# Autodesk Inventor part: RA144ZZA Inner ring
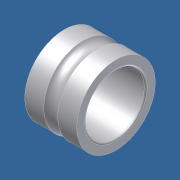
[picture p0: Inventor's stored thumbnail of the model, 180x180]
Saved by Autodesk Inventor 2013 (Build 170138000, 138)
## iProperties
Category: PARTsolutions
Created: 2011-07
Part Number: RA144ZZA Inner ring
Catalog Web Link: www.cadenas.de
Description: Six types ir - Inch system sizes
Document SubType Name: Modeling
Designer: PARTsolutions
Density: 1 g/cm^3
Material: Générique
NB: RA144ZZA Inner ring
NN: Six types ir
NT: Inch system sizes
NBSYN: RA144ZZA Inner ring
LINA: RA144ZZA Inner ring
SD: 3.175
D: 6.350
B: 2.380
B1: 2.779
D1: 7.52
D2: 7.52
C1: 0.58
C2: 0.79
R: 0.08
ORDER: RA144ZZA
CR: 284
COR: 96
CRF: 29
CORF: 10
LSG: 59000
LSO: 70000
MASS: 0.27
ORDER1: R144
WSS: RA144ZA
WDS: RA144ZZA
UTWF: FLR144
FORSS: FLRA144ZA
FORDS: FLRA144ZZA
DA1: 3.9
DA2: 4
DA: 5.5
RAS: 0.08
MASS1: 0.33
VERS: 3
X: 1.587
N: 9
O: 14.954
RB: 0.470
KT: DUMMY
SUPPLIER: NTN
ARTICLENO: RA144ZZA Inner ring
BOMINFO: RA144ZZA Inner ring
CREATOR: CADENAS GmbH
PSOL_IDENT_0: {\\10.0.0.251\ps_data\23d-libs\ntn\ball_roller_bearings\miniature_extra_small_bb\inch_system_sizes\i
PSOL_IDENT_1: ss_ir.prj},189 {VTYP=3D},{NB=RA144ZZA Inner ring},{LINA=RA144ZZA Inner ring},{NN=Six types ir},{DATE
PSOL_IDENT_2: =11.12.2007 08:48:22},{GEOMDATE=28.06.2007 13:01:00},{VERSION=},{LINEID=16080},{LINESUBID=-1},{WBVAR
PSOL_IDENT_3: =}  {NB=RA144ZZA Inner ring},{LINA=RA144ZZA Inner ring},{KT=DUMMY},{IDNR=},{SD=3.175},{D=6.350},{B=2
PSOL_IDENT_4: .380},{B1=2.779},{D1=7.52},{D2=7.52},{C1=0.58},{C2=0.79},{R=0.08},{ORDER=RA144ZZA},{CR=284},{COR=96}
PSOL_IDENT_5: ,{CRF=29},{CORF=10},{LSG=59000},{LSO=70000},{MASS=0.27},{ORDER1=R144},{WSS=RA144ZA},{WDS=RA144ZZA},{
PSOL_IDENT_6: UTWF=FLR144},{FORSS=FLRA144ZA},{FORDS=FLRA144ZZA},{DA1=3.9},{DA2=4},{DA=5.5},{RAS=0.08},{MASS1=0.33}
PSOL_IDENT_7: ,{VERS=3},{X=1.5875},{N=9},{O=14.95425},{RB=0.4699}
Title: RA144ZZA Inner ring
Author: Cadenas PARTsolutions
Comments: Inch system sizes
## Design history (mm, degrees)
sketch "Sketch_2"
  geometry: L1 (2.779, 0)-(0, 0); L2 (0, 2.096)-(0, 1.667); L3 (0.08, 1.587)-(2.699, 1.587); L4 (2.779, 1.667)-(2.779, 2.096); L5 (2.779, 2.096)-(1.763, 2.096); L6 (1.016, 2.096)-(0, 2.096); A1 r 0.08 centre (0.08, 1.668) between (0, 1.667) and (0.08, 1.587); A2 r 0.08 centre (2.699, 1.668) between (2.699, 1.587) and (2.779, 1.667); A3 r 0.47 centre (1.39, 2.381) between (1.016, 2.096) and (1.763, 2.096)
  constraints: 12 end point, 6 point on circle, 3 centre point
revolve "Revolution1" sketch "Sketch_2" stored, may be unused: angle "d0" = 360 deg
node "iss_ir_XY"
node "iss_ir_YZ"
node "iss_ir_ZX"
node "iss_ir_X"
node "iss_ir_Y"
node "iss_ir_Z"
node "iss_ir_Center"
node "Solide1"
node "Corps solides"
node "Corps surfaciques"
